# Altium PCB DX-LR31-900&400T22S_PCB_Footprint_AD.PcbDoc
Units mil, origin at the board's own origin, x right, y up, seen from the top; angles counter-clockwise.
Board outline 6000 x 4000 mil, 2 copper layers (Top Layer, Bottom Layer); 1 components, 0 nets, 22 pads, 0 vias.
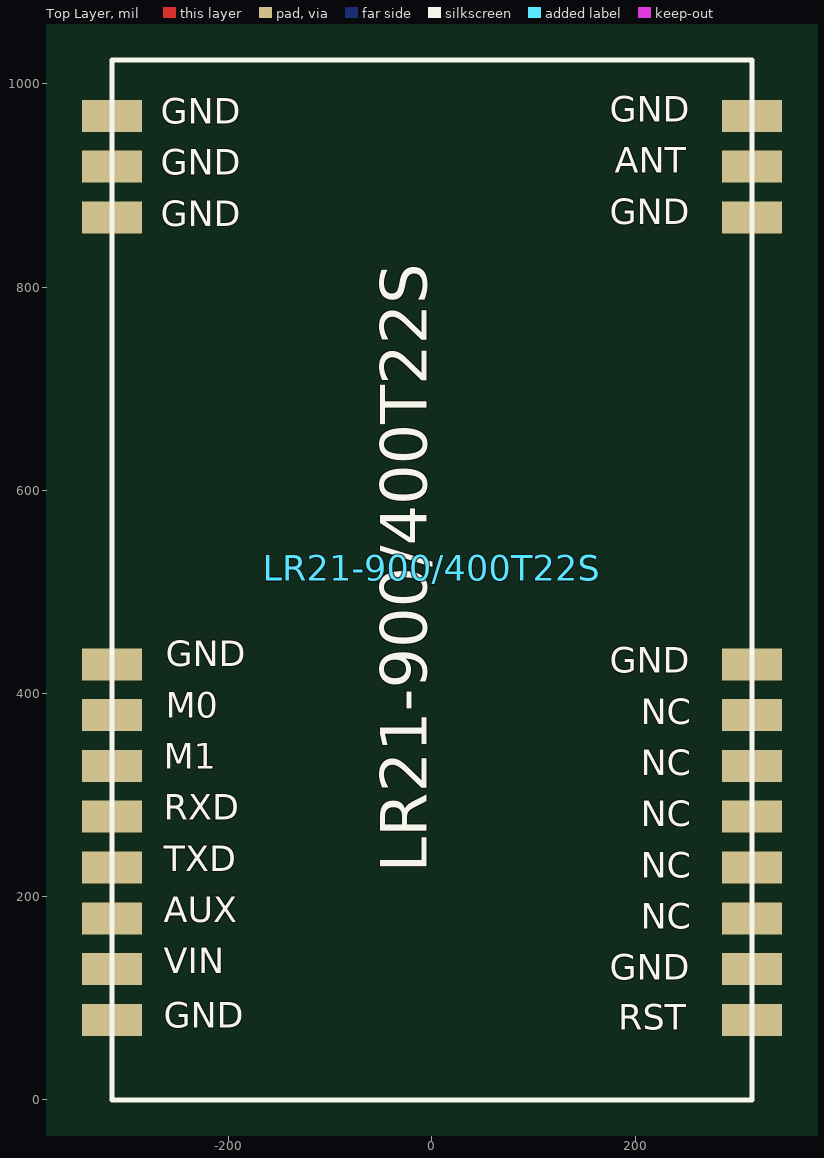
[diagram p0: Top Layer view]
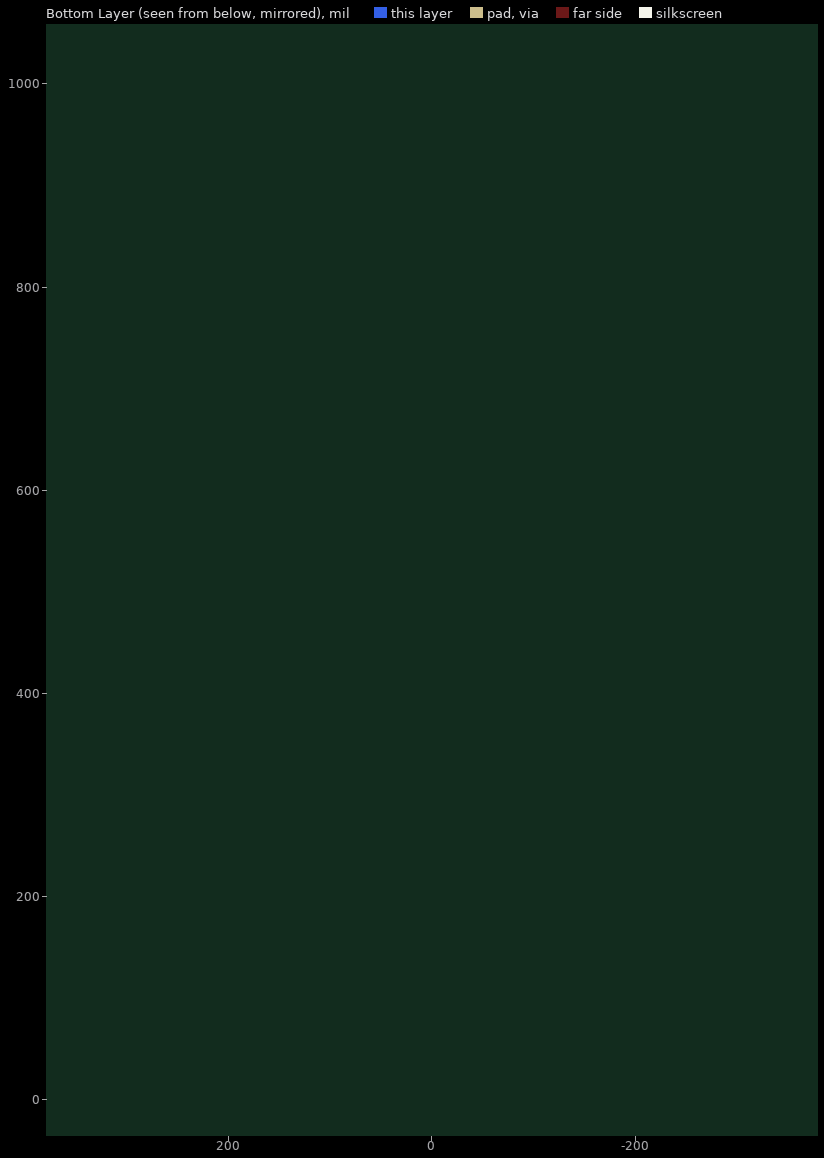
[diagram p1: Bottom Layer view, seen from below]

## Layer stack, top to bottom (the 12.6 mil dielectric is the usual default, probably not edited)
Top Solder: solder mask 0.4, Solder Resist, Dk 3.5
Top Layer: signal copper 1.4
Dielectric 1: dielectric 12.6, FR-4, Dk 4.8
Bottom Layer: signal copper 1.4
Bottom Solder: solder mask 0.4, Solder Resist, Dk 3.5

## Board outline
-2144.78,-1608.4 3855.22,-1608.4 3855.22,2391.6 -2144.78,2391.6

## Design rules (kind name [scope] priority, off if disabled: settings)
Clearance [All] p1: gap=10 ignorepadtopadclearanceinfootprint=FALSE except(0: Arc-Hole Track-Hole SMDPad-Hole THPad-Hole Via-Hole Fill-Hole Poly-Hole Region-Hole Text-Hole)
PolygonConnect [All] p1: connectstyle=Relief reliefconductorwidth=10 reliefentries=4 polygonreliefangle="90 Angle" airgapwidth=10
RoutingVias [All] p1: holewidth=28 width=50 viastyle="Through Hole" minholewidth=28 minwidth=50 maxholewidth=28 maxwidth=50
SolderMaskExpansion [All] p1: expansion=4 istentingtop=FALSE
Width [All] p1: maxlimit=10 minlimit=10 preferedwidth=10
30 further rules are at their usual default settings.

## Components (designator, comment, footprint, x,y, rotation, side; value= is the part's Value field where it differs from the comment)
LR21-900/400T22S "Comment" LR31-900/400T22S 0,0 r0 top

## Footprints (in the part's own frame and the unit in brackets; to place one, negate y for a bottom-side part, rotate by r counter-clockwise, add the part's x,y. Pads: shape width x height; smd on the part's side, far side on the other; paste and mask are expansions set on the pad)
LR31-900/400T22S [mm] "26mm**16mm*3.23mm-S"
  rect 1.5x0.8 smd: 1(-8,24.6) 2(-8,23.33) 3(-8,22.06) 4(-8,10.89) 5(-8,9.62) 6(-8,8.35) 7(-8,7.08) 8(-8,5.81) 9(-8,4.54) 10(-8,3.27) 11(-8,2) 12(8,2) 13(8,3.27) 14(8,4.54) 15(8,5.81) 16(8,7.08) 17(8,8.35) 18(8,9.62) 19(8,10.89) 20(8,22.06) 21(8,23.33) 22(8,24.6)
  silkscreen extent -8,0 8,26

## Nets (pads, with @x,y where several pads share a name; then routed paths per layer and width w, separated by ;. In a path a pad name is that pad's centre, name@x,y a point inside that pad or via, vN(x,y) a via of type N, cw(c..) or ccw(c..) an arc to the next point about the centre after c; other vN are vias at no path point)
pads on no net: LR21-900/400T22S.1 LR21-900/400T22S.2 LR21-900/400T22S.3 LR21-900/400T22S.4 LR21-900/400T22S.5 LR21-900/400T22S.6 LR21-900/400T22S.7 LR21-900/400T22S.8 LR21-900/400T22S.9 LR21-900/400T22S.10 LR21-900/400T22S.11 LR21-900/400T22S.12 LR21-900/400T22S.13 LR21-900/400T22S.14 LR21-900/400T22S.15 LR21-900/400T22S.16 LR21-900/400T22S.17 LR21-900/400T22S.18 LR21-900/400T22S.19 LR21-900/400T22S.20 LR21-900/400T22S.21 LR21-900/400T22S.22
